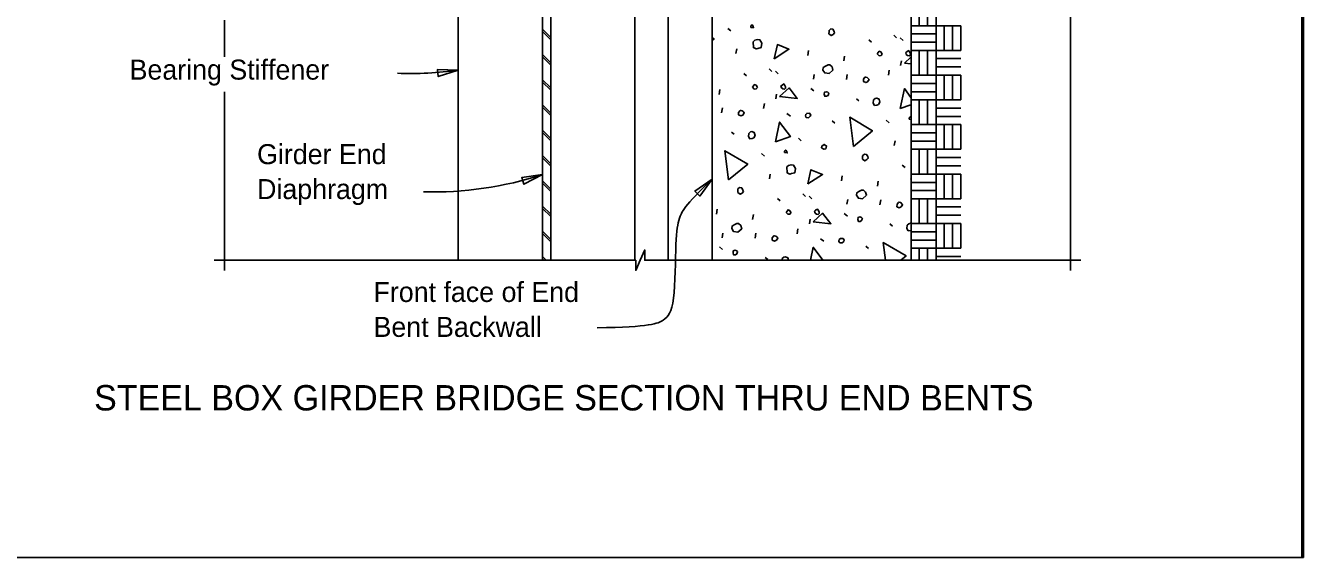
# Model space of a CAD drawing. Extents: x 0 to 30.8, y 0 to 21.2.
# Drawn here: x 21.15 to 30.8, y 0 to 4.02 of the extents above; entities that cross this region are included whole.
import ezdxf

# ---------------------------------------------------------------- set-up
doc = ezdxf.new("R2010")
doc.units = 0
for name, color, linetype in [('ActivePts-ConstElements', 7, 'Continuous'), ('Dimension', 7, 'Continuous'), ('Miscellaneous', 7, 'Continuous'), ('Miscellaneous1', 7, 'Continuous'), ('SteelGirder', 7, 'Continuous'), ('SupstrConc', 7, 'Continuous'), ('TextStructures', 7, 'Continuous')]:
    doc.layers.add(name, color=color, linetype=linetype)

msp = doc.modelspace()

# ---------------------------------------------------------------- linework, layer by layer
at = {"layer": 'ActivePts-ConstElements'}
msp.add_lwpolyline([(0, 0), (30.7879, 0), (30.7879, 19.4596), (0, 19.4596)], close=True, dxfattribs=at)
at = {"layer": 'Dimension'}
for points in [[(29.0415, 2.169), (29.0415, 4.3387)], [(22.6555, 3.7827), (22.6555, 4.0614)], [(22.6555, 2.169), (22.6555, 3.5185)], [(29.119, 2.2465), (25.8285, 2.2465), (25.8285, 2.324), (25.7948, 2.2465), (25.761, 2.169), (25.761, 2.2465), (22.578, 2.2465)]]:
    msp.add_lwpolyline(points, dxfattribs=at)
for points in [[(24.4213, 3.6828), (24.2629, 3.6874), (24.2702, 3.635)], [(25.0567, 2.8948), (24.9165, 2.8212), (24.9001, 2.8715)], [(26.338, 2.8592), (26.2441, 2.7316), (26.2073, 2.7697)]]:
    msp.add_lwpolyline(points, close=True, dxfattribs=at)
for centre, start, end in [((24.058, 6.2846), 267.88954, 277.94853), ((24.2338, 5.3897), 268.34066, 288.25581)]:
    msp.add_arc(centre, 2.6271, start, end, dxfattribs=at)
msp.add_open_spline([(25.4682, 1.7365), (25.8745, 1.7418), (25.9798, 1.7919), (26.0595, 1.8813), (26.0595, 2.4367), (26.0859, 2.5594), (26.1236, 2.6576), (26.338, 2.8592)], degree=3, dxfattribs=at)
at = {"layer": 'Miscellaneous'}
for p, q in [((28.0267, 4.019), (28.0267, 4.3928)), ((27.9005, 4.2065), (27.9005, 4.019)), ((27.963, 4.2065), (27.963, 4.019)), ((25.1192, 3.9302), (25.0568, 3.9926)), ((25.1192, 3.9126), (25.0568, 3.975)), ((26.4548, 3.999), (26.4782, 3.9794)), ((27.838, 4.019), (28.0267, 4.019)), ((27.838, 3.9565), (28.0267, 3.9565)), ((28.0267, 3.6453), (28.0267, 4.019)), ((28.0267, 4.019), (28.213, 4.019)), ((28.088, 3.8328), (28.088, 4.019)), ((28.1505, 3.8328), (28.1505, 4.019)), ((28.213, 3.8328), (28.213, 4.019)), ((27.5187, 3.9114), (27.539, 3.8935)), ((27.7085, 3.9467), (27.7295, 3.9265)), ((27.7574, 3.9287), (27.7783, 3.9085)), ((27.838, 3.894), (28.0267, 3.894)), ((25.1192, 3.7393), (25.0568, 3.8017)), ((25.1192, 3.7216), (25.0568, 3.784)), ((26.5162, 3.8084), (26.5223, 3.8437)), ((27.0586, 3.7933), (27.064, 3.831)), ((27.331, 3.7524), (27.3364, 3.7901)), ((27.838, 3.8328), (28.213, 3.8328)), ((27.838, 3.8328), (27.838, 3.6453)), ((27.9005, 3.8328), (27.9005, 3.6453)), ((27.963, 3.8328), (27.963, 3.6453)), ((28.0267, 3.7703), (28.213, 3.7703)), ((26.7668, 3.6944), (26.7877, 3.6741)), ((26.8156, 3.6764), (26.8365, 3.6561)), ((27.6675, 3.6459), (27.6729, 3.6835)), ((27.7591, 3.7196), (27.7651, 3.7548)), ((28.0267, 3.7078), (28.213, 3.7078)), ((25.1192, 3.5484), (25.0568, 3.6108)), ((25.1192, 3.5307), (25.0568, 3.5931)), ((26.5769, 3.659), (26.5972, 3.6412)), ((27.101, 3.6157), (27.1071, 3.651)), ((27.3503, 3.6126), (27.3557, 3.6503)), ((27.838, 3.6453), (28.0267, 3.6453)), ((27.838, 3.5828), (28.0267, 3.5828)), ((28.0267, 3.6453), (28.213, 3.6453)), ((28.0267, 3.2715), (28.0267, 3.6453)), ((28.088, 3.459), (28.088, 3.6453)), ((28.1505, 3.459), (28.1505, 3.6453)), ((28.213, 3.459), (28.213, 3.6453)), ((26.3892, 3.5), (26.3946, 3.5377)), ((26.8173, 3.4672), (26.8234, 3.5025)), ((27.081, 3.5456), (27.1043, 3.526)), ((27.838, 3.5203), (28.0267, 3.5203)), ((25.1192, 3.3575), (25.0568, 3.4199)), ((25.1192, 3.3398), (25.0568, 3.4022)), ((26.4085, 3.3603), (26.414, 3.398)), ((26.7257, 3.3935), (26.7312, 3.4312)), ((27.4255, 3.4671), (27.4452, 3.4517)), ((27.838, 3.459), (28.213, 3.459)), ((27.838, 3.459), (27.838, 3.2715)), ((27.9005, 3.459), (27.9005, 3.2715)), ((27.963, 3.459), (27.963, 3.2715)), ((28.0267, 3.3965), (28.213, 3.3965)), ((26.9016, 3.3552), (26.9274, 3.3363)), ((27.2428, 3.2991), (27.2631, 3.2813)), ((27.6502, 3.3048), (27.6736, 3.2851)), ((28.0267, 3.334), (28.213, 3.334)), ((25.1192, 3.1666), (25.0568, 3.229)), ((25.1192, 3.1489), (25.0568, 3.2113)), ((26.4837, 3.2148), (26.5034, 3.1993)), ((27.838, 3.2715), (28.0267, 3.2715)), ((27.838, 3.209), (28.0267, 3.209)), ((28.0267, 2.8978), (28.0267, 3.2715)), ((28.0267, 3.2715), (28.213, 3.2715)), ((28.088, 3.0853), (28.088, 3.2715)), ((28.1505, 3.0853), (28.1505, 3.2715)), ((28.213, 3.0853), (28.213, 3.2715)), ((26.9878, 3.1687), (27.0088, 3.1484)), ((27.7116, 3.1142), (27.7177, 3.1494)), ((27.838, 3.1465), (28.0267, 3.1465)), ((25.1192, 2.9756), (25.0568, 3.038)), ((25.1192, 2.958), (25.0568, 3.0204)), ((26.7084, 3.0524), (26.7318, 3.0328)), ((27.838, 3.0853), (28.213, 3.0853)), ((27.838, 3.0853), (27.838, 2.8978)), ((27.9005, 3.0853), (27.9005, 2.8978)), ((27.963, 3.0853), (27.963, 2.8978)), ((28.0267, 3.0228), (28.213, 3.0228)), ((26.7698, 2.8618), (26.7759, 2.8971)), ((27.7724, 2.9648), (27.7927, 2.9469)), ((27.838, 2.8978), (28.0267, 2.8978)), ((28.0267, 2.9603), (28.213, 2.9603)), ((28.0267, 2.8978), (28.213, 2.8978)), ((28.0267, 2.524), (28.0267, 2.8978)), ((28.088, 2.7115), (28.088, 2.8978)), ((28.1505, 2.7115), (28.1505, 2.8978)), ((28.213, 2.7115), (28.213, 2.8978)), ((25.1192, 2.7847), (25.0568, 2.8471)), ((25.1192, 2.7671), (25.0568, 2.8294)), ((27.3122, 2.8467), (27.3177, 2.8844)), ((27.5846, 2.8058), (27.59, 2.8435)), ((27.838, 2.8353), (28.0267, 2.8353)), ((26.8306, 2.7124), (26.8509, 2.6946)), ((27.0204, 2.7478), (27.0414, 2.7275)), ((27.0692, 2.7298), (27.0902, 2.7095)), ((27.3547, 2.6691), (27.3607, 2.7044)), ((27.6039, 2.666), (27.6094, 2.7037)), ((27.838, 2.7728), (28.0267, 2.7728)), ((27.838, 2.7115), (28.213, 2.7115)), ((27.838, 2.7115), (27.838, 2.524)), ((27.9005, 2.7115), (27.9005, 2.524)), ((27.963, 2.7115), (27.963, 2.524)), ((25.1192, 2.5938), (25.0568, 2.6562)), ((25.1192, 2.5761), (25.0568, 2.6385)), ((26.3705, 2.5943), (26.3759, 2.632)), ((28.0267, 2.649), (28.213, 2.649)), ((26.6428, 2.5534), (26.6483, 2.5911)), ((27.0709, 2.5206), (27.077, 2.5559)), ((27.3346, 2.599), (27.358, 2.5794)), ((27.6792, 2.5205), (27.6988, 2.5051)), ((27.838, 2.524), (28.0267, 2.524)), ((28.0267, 2.5865), (28.213, 2.5865)), ((28.0267, 2.2466), (28.0267, 2.5241)), ((28.0267, 2.524), (28.213, 2.524)), ((28.088, 2.3378), (28.088, 2.524)), ((28.1505, 2.3378), (28.1505, 2.524)), ((28.213, 2.3378), (28.213, 2.524)), ((25.1192, 2.4029), (25.0568, 2.4653)), ((25.1192, 2.3852), (25.0568, 2.4476)), ((26.4129, 2.4168), (26.419, 2.452)), ((26.6622, 2.4137), (26.6676, 2.4514)), ((26.9794, 2.4469), (26.9848, 2.4846)), ((27.838, 2.4615), (28.0267, 2.4615)), ((26.3928, 2.3467), (26.4162, 2.3271)), ((27.1553, 2.4086), (27.1811, 2.3897)), ((27.4964, 2.3525), (27.5167, 2.3347)), ((27.838, 2.399), (28.0267, 2.399)), ((27.838, 2.3378), (28.213, 2.3378)), ((27.9005, 2.3378), (27.9005, 2.2466)), ((27.963, 2.3378), (27.963, 2.2466)), ((25.0846, 2.2465), (25.0568, 2.2744)), ((25.0669, 2.2465), (25.0568, 2.2567)), ((26.7374, 2.2682), (26.757, 2.2527)), ((28.0267, 2.2753), (28.213, 2.2753))]:
    msp.add_line(p, q, dxfattribs=at)
for points in [[(26.6287, 4.0068), (26.65, 4.0047), (26.6474, 4.0144), (26.6393, 4.0252), (26.6285, 4.0171), (26.6287, 4.0068)], [(27.2193, 3.9761), (27.219, 3.9579), (27.2356, 3.9442), (27.2512, 3.9536), (27.2613, 3.9641), (27.2581, 3.9761), (27.2487, 3.9917), (27.2323, 3.9951), (27.2197, 3.984), (27.2193, 3.9761)], [(26.3379, 3.9278), (26.3518, 3.9197), (26.3379, 3.9082)], [(26.6475, 3.8979), (26.6488, 3.8543), (26.6696, 3.8443), (26.6817, 3.8476), (26.7083, 3.8547), (26.7126, 3.8869), (26.6982, 3.9115), (26.6794, 3.9143), (26.6601, 3.9091), (26.6475, 3.8979)], [(26.8061, 3.7696), (26.8292, 3.8767), (26.9165, 3.8406), (26.8061, 3.7696)], [(27.5829, 3.807), (27.5971, 3.7926), (27.6123, 3.7941), (27.62, 3.8039), (27.6187, 3.8088), (27.61, 3.822), (27.5984, 3.8266), (27.5906, 3.8168), (27.5829, 3.807)], [(27.7885, 3.7352), (27.8379, 3.7811)], [(27.802, 3.8009), (27.8118, 3.7932), (27.8252, 3.7916), (27.8335, 3.799), (27.8333, 3.8093), (27.8277, 3.8208), (27.8196, 3.8316), (27.8064, 3.8228), (27.7981, 3.8154), (27.802, 3.8009)], [(27.1732, 3.6842), (27.1869, 3.662), (27.2192, 3.6577), (27.2484, 3.6837), (27.242, 3.7078), (27.2247, 3.7239), (27.212, 3.7231), (27.1916, 3.7124), (27.1759, 3.7031), (27.1732, 3.6842)], [(27.8379, 3.7302), (27.7885, 3.7352)], [(26.6412, 3.5546), (26.6553, 3.5403), (26.6705, 3.5418), (26.6782, 3.5516), (26.6769, 3.5564), (26.6682, 3.5696), (26.6566, 3.5743), (26.6489, 3.5644), (26.6412, 3.5546)], [(26.8602, 3.5486), (26.87, 3.5409), (26.8834, 3.5393), (26.8917, 3.5467), (26.8916, 3.557), (26.8859, 3.5684), (26.8779, 3.5792), (26.8647, 3.5705), (26.8563, 3.5631), (26.8602, 3.5486)], [(27.4788, 3.616), (27.4785, 3.5978), (27.4962, 3.5896), (27.5101, 3.5959), (27.5213, 3.6119), (27.5133, 3.6226), (27.5065, 3.6286), (27.4955, 3.6308), (27.4907, 3.6295), (27.4788, 3.616)], [(26.8467, 3.4829), (26.9172, 3.5483), (26.9798, 3.4693), (26.8467, 3.4829)], [(27.1836, 3.5007), (27.1875, 3.4862), (27.2002, 3.487), (27.2116, 3.4926), (27.2174, 3.5097), (27.2106, 3.5157), (27.199, 3.5203), (27.1845, 3.5164), (27.1836, 3.5007)], [(27.7561, 3.3926), (27.7881, 3.5436), (27.8379, 3.476)], [(26.537, 3.3636), (26.5367, 3.3455), (26.5545, 3.3373), (26.5683, 3.3436), (26.5795, 3.3595), (26.5715, 3.3703), (26.5647, 3.3762), (26.5538, 3.3785), (26.5489, 3.3772), (26.537, 3.3636)], [(27.5548, 3.4578), (27.5534, 3.4341), (27.5634, 3.4161), (27.581, 3.4182), (27.5924, 3.4239), (27.603, 3.4422), (27.5972, 3.464), (27.5795, 3.4721), (27.5674, 3.4689), (27.5548, 3.4578)], [(27.8379, 3.4221), (27.7561, 3.3926)], [(26.8143, 3.1403), (26.8463, 3.2912), (26.9276, 3.181), (26.8143, 3.1403)], [(27.0434, 3.3285), (27.0495, 3.325), (27.0653, 3.324), (27.0778, 3.3351), (27.0807, 3.3437), (27.072, 3.3569), (27.0514, 3.3565), (27.043, 3.3491), (27.0408, 3.3382), (27.0434, 3.3285)], [(27.4031, 3.1065), (27.3751, 3.3268), (27.5472, 3.2254), (27.4031, 3.1065)], [(27.8379, 3.3266), (27.8347, 3.3309), (27.8239, 3.3228), (27.8241, 3.3125)], [(27.8241, 3.3125), (27.8379, 3.3112)], [(26.6131, 3.2054), (26.6116, 3.1818), (26.6217, 3.1637), (26.6392, 3.1659), (26.6506, 3.1715), (26.6612, 3.1899), (26.6554, 3.2116), (26.6377, 3.2198), (26.6256, 3.2166), (26.6131, 3.2054)], [(27.1625, 3.0964), (27.1809, 3.0858), (27.1954, 3.0897), (27.2005, 3.1092), (27.1815, 3.1222), (27.1731, 3.1148), (27.1641, 3.1098), (27.1625, 3.0964), (27.1612, 3.1013)], [(26.4613, 2.8542), (26.4333, 3.0745), (26.6055, 2.9731), (26.4613, 2.8542)], [(26.8823, 3.0602), (26.9036, 3.0581), (26.901, 3.0678), (26.8929, 3.0786), (26.8822, 3.0705), (26.8823, 3.0602)], [(27.4729, 3.0295), (27.4726, 3.0113), (27.4892, 2.9976), (27.5048, 3.007), (27.515, 3.0175), (27.5117, 3.0295), (27.5024, 3.0451), (27.4859, 3.0485), (27.4734, 3.0374), (27.4729, 3.0295)], [(26.9011, 2.9513), (26.9025, 2.9077), (26.9233, 2.8977), (26.9353, 2.901), (26.9619, 2.9081), (26.9662, 2.9403), (26.9519, 2.9649), (26.933, 2.9676), (26.9137, 2.9625), (26.9011, 2.9513)], [(27.0598, 2.823), (27.0828, 2.9301), (27.1702, 2.894), (27.0598, 2.823)], [(27.8379, 2.8621), (27.8366, 2.8603)], [(27.8366, 2.8603), (27.8379, 2.859)], [(26.5311, 2.7771), (26.5308, 2.7589), (26.5474, 2.7453), (26.563, 2.7546), (26.5732, 2.7651), (26.5699, 2.7772), (26.5606, 2.7928), (26.5441, 2.7962), (26.5316, 2.785), (26.5311, 2.7771)], [(27.4269, 2.7376), (27.4406, 2.7154), (27.4728, 2.7111), (27.5021, 2.7371), (27.4956, 2.7612), (27.4784, 2.7773), (27.4656, 2.7765), (27.4452, 2.7658), (27.4296, 2.7565), (27.4269, 2.7376)], [(26.8948, 2.608), (26.909, 2.5937), (26.9241, 2.5952), (26.9318, 2.605), (26.9305, 2.6098), (26.9218, 2.623), (26.9102, 2.6277), (26.9025, 2.6178), (26.8948, 2.608)], [(27.1138, 2.602), (27.1236, 2.5943), (27.137, 2.5927), (27.1454, 2.6001), (27.1452, 2.6104), (27.1396, 2.6218), (27.1315, 2.6326), (27.1183, 2.6239), (27.1099, 2.6165), (27.1138, 2.602)], [(27.7324, 2.6694), (27.7321, 2.6512), (27.7499, 2.643), (27.7637, 2.6493), (27.775, 2.6653), (27.7669, 2.676), (27.7601, 2.682), (27.7492, 2.6842), (27.7443, 2.6829), (27.7324, 2.6694)], [(26.4851, 2.4853), (26.4988, 2.4631), (26.531, 2.4588), (26.5603, 2.4847), (26.5538, 2.5089), (26.5366, 2.525), (26.5239, 2.5241), (26.5034, 2.5135), (26.4878, 2.5041), (26.4851, 2.4853)], [(27.1004, 2.5363), (27.1708, 2.6017), (27.2334, 2.5227), (27.1004, 2.5363)], [(27.4372, 2.5541), (27.4411, 2.5396), (27.4538, 2.5404), (27.4653, 2.546), (27.471, 2.5631), (27.4643, 2.5691), (27.4527, 2.5737), (27.4382, 2.5698), (27.4372, 2.5541)], [(27.8085, 2.5112), (27.8071, 2.4875), (27.8171, 2.4695), (27.8346, 2.4716), (27.8379, 2.4732)], [(27.8379, 2.5233), (27.8331, 2.5255), (27.821, 2.5223), (27.8085, 2.5112)], [(26.7907, 2.417), (26.7904, 2.3988), (26.8081, 2.3907), (26.8219, 2.397), (26.8332, 2.4129), (26.8251, 2.4237), (26.8184, 2.4296), (26.8074, 2.4319), (26.8026, 2.4306), (26.7907, 2.417)], [(26.4955, 2.3017), (26.4993, 2.2872), (26.5121, 2.288), (26.5235, 2.2937), (26.5293, 2.3108), (26.5225, 2.3167), (26.5109, 2.3214), (26.4964, 2.3175), (26.4955, 2.3017)], [(27.0792, 2.2466), (27.1, 2.3446), (27.1722, 2.2466)], [(27.297, 2.3819), (27.3031, 2.3784), (27.3189, 2.3774), (27.3315, 2.3885), (27.3344, 2.3971), (27.3257, 2.4103), (27.305, 2.4099), (27.2967, 2.4025), (27.2944, 2.3916), (27.297, 2.3819)], [(27.6457, 2.2466), (27.6288, 2.3802), (27.8009, 2.2788), (27.7619, 2.2466)], [(26.8667, 2.2588), (26.866, 2.2466)], [(26.914, 2.2466), (26.9091, 2.265), (26.8913, 2.2732), (26.8793, 2.27), (26.8667, 2.2588)]]:
    msp.add_lwpolyline(points, dxfattribs=at)
at = {"layer": 'Miscellaneous1'}
msp.add_lwpolyline([(0, 19.8), (30.8, 19.8), (30.8, 0), (0, 0)], close=True, dxfattribs=at)
at = {"layer": 'SteelGirder'}
for p, q in [((26.0047, 2.2465), (26.0047, 6.7147)), ((25.0568, 2.2465), (25.0568, 6.6314)), ((25.1192, 2.2465), (25.1192, 6.6314)), ((25.7547, 2.2465), (25.7547, 6.4742)), ((24.4213, 2.2465), (24.4213, 5.6138))]:
    msp.add_line(p, q, dxfattribs=at)
at = {"layer": 'SupstrConc'}
for p, q in [((26.338, 6.7147), (26.338, 2.2466)), ((27.838, 2.2465), (27.838, 6.7147))]:
    msp.add_line(p, q, dxfattribs=at)

# ---------------------------------------------------------------- texts
at = {"layer": 'Dimension'}
for s, p in [('Girder End', (22.9023, 2.9727)), ('Diaphragm', (22.9023, 2.7087)), ('Front face of End ', (23.7811, 1.9311)), ('Bent Backwall', (23.7811, 1.6671))]:
    msp.add_text(s, height=0.1512, dxfattribs=at).set_placement(p)
at = {"layer": 'TextStructures'}
for s, height, p in [('Bearing Stiffener', 0.1512, (21.9401, 3.6116)), ('STEEL BOX GIRDER BRIDGE SECTION THRU END BENTS', 0.192, (21.6723, 1.111))]:
    msp.add_text(s, height=height, dxfattribs=at).set_placement(p)

doc.saveas('drawing.dxf')
